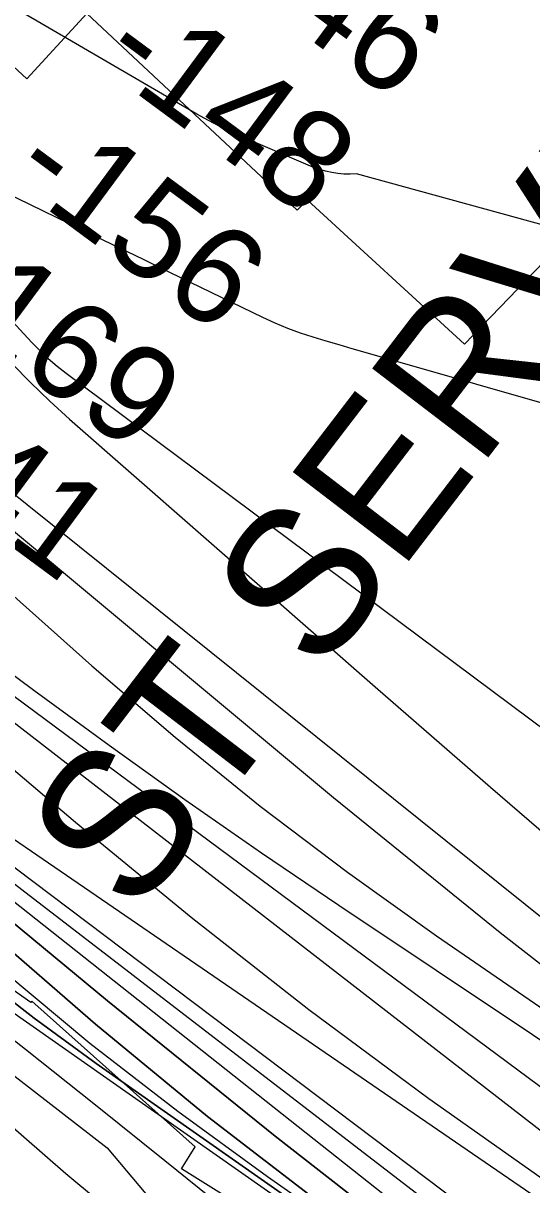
# Model space of a CAD drawing. Extents: x 3651524 to 3689615, y 505651 to 531377.
# Drawn here: x 3659786 to 3660133, y 515628 to 516422 of the extents above; entities that cross this region are included whole.
import ezdxf

# ---------------------------------------------------------------- set-up
doc = ezdxf.new("R2010")
doc.units = 0
for name, color, linetype in [('V-CHAN-NAID', 7, 'Continuous'), ('V-RIVR-RANG', 7, 'Continuous'), ('V-RRAP-FSHR', 7, 'Continuous'), ('V-RRAP-RVMT', 7, 'Continuous'), ('V-TOPO-DPTH', 7, 'Continuous'), ('V-TOPO-MAJR', 7, 'Continuous'), ('V-TOPO-MINR', 7, 'Continuous'), ('V-TOPO-WATR', 7, 'Continuous')]:
    doc.layers.add(name, color=color, linetype=linetype)

msp = doc.modelspace()

# ---------------------------------------------------------------- linework, layer by layer
at = {"layer": 'V-RRAP-FSHR'}
msp.add_lwpolyline([(3659396.851, 515999.135), (3659842.953, 515653.316), (3660038.76, 515420.179), (3660353.083, 515152.532), (3660556.566, 515075.917), (3660792.389, 514981.084), (3661161.297, 514923.914), (3661473.843, 514844.374), (3661744.117, 514711.391), (3661981.087, 514567.222), (3662157.856, 514447.912), (3662424.289, 514303.745)], dxfattribs=at)
at = {"layer": 'V-RRAP-RVMT'}
msp.add_line((3659791.482, 515753.456), (3659790.823, 515752.695), dxfattribs=at)
for points in [[(3659651.793, 516510.376), (3659788.091, 516384.184), (3659829.17, 516428.811), (3659972.803, 516294.337), (3659979.872, 516301.076), (3660087.089, 516202.755), (3660293.017, 516416.547)], [(3659790.823, 515752.695), (3659620.383, 515872.74), (3659609.659, 515863.086), (3659443.462, 515984.102), (3659438.2, 515978.971), (3659260.198, 516110.348), (3659147.603, 516287.133), (3659155.699, 516293.328), (3659039.216, 516470.131)], [(3660212.139, 515294.417), (3660053.726, 515429.09), (3660087.126, 515471.484), (3659930.09, 515612.317), (3659932.054, 515614.896), (3659893.694, 515638.795), (3659903.071, 515653.931), (3659791.482, 515753.456)]]:
    msp.add_lwpolyline(points, dxfattribs=at)
at = {"layer": 'V-TOPO-DPTH'}
for points in [[(3658899.589, 516724.07), (3659568.117, 515898.581), (3659572.31, 515893.572), (3659576.607, 515888.659), (3659581.063, 515883.889), (3659585.624, 515879.213), (3659590.344, 515874.7), (3659595.17, 515870.309), (3659600.157, 515866.1), (3659605.25, 515862.013), (3659691.304, 515795.545), (3659739.384, 515758.163), (3659787.304, 515720.577), (3659834.982, 515682.686), (3659882.5, 515644.592), (3660240.174, 515355.97)], [(3658899.589, 516724.07), (3659568.117, 515898.581), (3659572.31, 515893.572), (3659576.607, 515888.659), (3659581.063, 515883.889), (3659585.624, 515879.213), (3659590.344, 515874.7), (3659595.17, 515870.309), (3659600.157, 515866.1), (3659605.25, 515862.013), (3659691.304, 515795.545), (3659739.384, 515758.163), (3659787.304, 515720.577), (3659834.982, 515682.686), (3659882.5, 515644.592), (3660240.174, 515355.97)], [(3660561.202, 515201.855), (3659835.435, 515710.798), (3659793.122, 515741.866), (3659751.77, 515774.113), (3659711.861, 515808.128), (3659672.914, 515843.323), (3659640.641, 515873.787), (3659618.931, 515894.995), (3659597.723, 515916.676), (3659577.268, 515939.069), (3659557.315, 515961.937), (3659041.277, 516574.153)], [(3660561.202, 515201.855), (3659835.435, 515710.798), (3659793.122, 515741.866), (3659751.77, 515774.113), (3659711.861, 515808.128), (3659672.914, 515843.323), (3659640.641, 515873.787), (3659618.931, 515894.995), (3659597.723, 515916.676), (3659577.268, 515939.069), (3659557.315, 515961.937), (3659041.277, 516574.153)], [(3659203.997, 516455.422), (3659249.099, 516392.961), (3659295.447, 516331.445), (3659342.802, 516270.736), (3659391.669, 516211.237), (3659441.543, 516152.545), (3659606.563, 515963.224), (3659613.614, 515955.573), (3659620.93, 515948.198), (3659628.642, 515941.238), (3659636.618, 515934.556), (3660059.734, 515599.534), (3660149.273, 515529.938)], [(3659203.997, 516455.422), (3659249.099, 516392.961), (3659295.447, 516331.445), (3659342.802, 516270.736), (3659391.669, 516211.237), (3659441.543, 516152.545), (3659606.563, 515963.224), (3659613.614, 515955.573), (3659620.93, 515948.198), (3659628.642, 515941.238), (3659636.618, 515934.556), (3660059.734, 515599.534), (3660149.273, 515529.938)], [(3659193.993, 516433.801), (3659232.704, 516384.43), (3659272.616, 516336.025), (3659313.331, 516288.265), (3659597.717, 515962.858), (3659607.129, 515952.6), (3659616.854, 515942.662), (3659627.047, 515933.206), (3659637.553, 515924.071), (3659843.231, 515753.783), (3659957.9, 515661.174), (3660074.019, 515570.468), (3660192.31, 515482.615)], [(3660192.31, 515482.615), (3660074.019, 515570.468), (3659957.9, 515661.174), (3659843.231, 515753.783), (3659637.553, 515924.071), (3659627.047, 515933.206), (3659616.854, 515942.662), (3659607.129, 515952.6), (3659597.717, 515962.858), (3659313.331, 516288.265), (3659272.616, 516336.025), (3659232.704, 516384.43), (3659193.993, 516433.801)], [(3659180.088, 516429.198), (3659588.863, 515962.484), (3659600.589, 515949.567), (3659612.61, 515936.939), (3659625.072, 515924.746), (3659637.827, 515912.843), (3659759.825, 515802.994), (3659834.938, 515737.814), (3659911.561, 515674.532), (3659990.449, 515614.098), (3660070.848, 515555.562), (3660572.282, 515204.361)], [(3660572.282, 515204.361), (3660070.848, 515555.562), (3659990.449, 515614.098), (3659911.561, 515674.532), (3659834.938, 515737.814), (3659759.825, 515802.994), (3659637.827, 515912.843), (3659625.072, 515924.746), (3659612.61, 515936.939), (3659600.589, 515949.567), (3659588.863, 515962.484), (3659180.088, 516429.198)]]:
    msp.add_lwpolyline(points, dxfattribs=at)
at = {"layer": 'V-TOPO-MAJR'}
for points in [[(3660956.257, 516059.962), (3660013.267, 516319.219), (3660009.034, 516318.975), (3660004.814, 516318.99), (3660000.613, 516319.392), (3659996.425, 516320.053), (3659992.285, 516321.035), (3659988.196, 516322.18), (3659984.185, 516323.57), (3659980.224, 516325.123), (3659936.905, 516343.645), (3659928.575, 516347.392), (3659920.346, 516351.34), (3659912.27, 516355.592), (3659904.295, 516360.045), (3659720.25, 516467.359)], [(3659368.191, 516459.155), (3659420.277, 516387.593), (3659471.403, 516315.318), (3659556.923, 516191.782), (3659564.525, 516180.71), (3659572.069, 516169.598), (3659579.527, 516158.429), (3659586.927, 516147.22), (3659594.524, 516136.166), (3659602.436, 516125.354), (3659610.825, 516114.908), (3659619.53, 516104.704), (3659673.997, 516043.678), (3659678.993, 516038.414), (3659684.188, 516033.368), (3659689.682, 516028.648), (3659695.375, 516024.147), (3660621.19, 515337.071)], [(3659546.094, 516453.45), (3659571.779, 516419.553), (3659598.852, 516386.755), (3659626.851, 516354.689), (3659765.241, 516202.7), (3659777.769, 516189.395), (3659790.583, 516176.381), (3659803.824, 516163.802), (3659817.35, 516151.514), (3659947.204, 516037.454), (3660026.008, 515968.511), (3660104.993, 515899.777), (3660184.25, 515831.357)], [(3659235.003, 516451.101), (3659274.641, 516394.713), (3659314.807, 516338.69), (3659364.764, 516270.025), (3659405.663, 516215.315), (3659447.485, 516161.339), (3659490.691, 516108.465), (3659534.82, 516056.324), (3659615.398, 515963.581), (3659620.073, 515958.515), (3659624.936, 515953.649), (3659630.082, 515949.082), (3659635.416, 515944.715), (3660311.335, 515424.312)]]:
    msp.add_lwpolyline(points, dxfattribs=at)
at = {"layer": 'V-TOPO-MINR'}
for points in [[(3658970.75, 516648.522), (3659549.511, 515948.184), (3659568.629, 515925.82), (3659588.227, 515903.9), (3659608.546, 515882.646), (3659629.344, 515861.835), (3659650.947, 515841.895), (3659673.137, 515822.666), (3659696.21, 515804.505), (3659719.87, 515787.056), (3660555.664, 515200.604)], [(3659041.277, 516574.153), (3659557.315, 515961.937), (3659577.268, 515939.069), (3659597.723, 515916.676), (3659618.931, 515894.995), (3659640.641, 515873.787), (3659672.914, 515843.323), (3659711.861, 515808.128), (3659751.77, 515774.113), (3659793.122, 515741.866), (3659835.435, 515710.798), (3660561.202, 515201.855)], [(3659111.116, 516500.99), (3659574.163, 515962.172), (3659589.741, 515944.672), (3659605.711, 515927.551), (3659622.268, 515910.997), (3659639.217, 515894.822), (3659716.406, 515823.691), (3659773.198, 515773.419), (3659831.257, 515724.722), (3659891.218, 515678.385), (3659952.445, 515633.622), (3660566.742, 515203.107)], [(3659338.624, 516463.63), (3659384.563, 516399.642), (3659447.143, 516310.674), (3659461.087, 516290.646), (3659474.903, 516270.531), (3659488.527, 516250.286), (3659502.022, 516229.952), (3659515.849, 516209.883), (3659530.247, 516190.252), (3659545.499, 516171.277), (3659561.321, 516152.739), (3659659.251, 516043.018), (3659668.232, 516033.496), (3659677.539, 516024.324), (3659687.334, 516015.676), (3659697.456, 516007.377), (3660161.927, 515647.448)], [(3659101.398, 516453.858), (3659543.399, 515883.69), (3659551.15, 515874.223), (3659559.217, 515865.049), (3659567.761, 515856.316), (3659576.621, 515847.878), (3659728.439, 515710.79), (3659814.714, 515635.609), (3659902.672, 515562.53), (3659993.157, 515492.603), (3660085.326, 515424.778), (3660520.018, 515116.583)], [(3659203.997, 516455.422), (3659249.099, 516392.961), (3659295.447, 516331.445), (3659342.802, 516270.736), (3659391.669, 516211.237), (3659441.543, 516152.545), (3659606.563, 515963.224), (3659613.614, 515955.573), (3659620.93, 515948.198), (3659628.642, 515941.238), (3659636.618, 515934.556), (3660059.734, 515599.534), (3660149.273, 515529.938)], [(3659432.2, 516457.485), (3659461.448, 516419.304), (3659490.529, 516380.996), (3659519.568, 516342.654), (3659548.715, 516304.395), (3659578.025, 516266.261), (3659607.444, 516228.21), (3659688.305, 516124.081), (3659704.987, 516103.778), (3659722.371, 516084.132), (3659740.809, 516065.472), (3659759.949, 516047.468), (3659832.582, 515982.82), (3659889.436, 515934.095), (3659947.444, 515886.842), (3660007.183, 515841.796), (3660068.074, 515798.221), (3660676.381, 515379.934)], [(3659460.762, 516460.262), (3659560.278, 516331.812), (3659574.569, 516313.235), (3659588.775, 516294.593), (3659602.852, 516275.855), (3659616.844, 516257.052), (3659630.96, 516238.35), (3659645.328, 516219.847), (3659660.074, 516201.644), (3659675.07, 516183.64), (3659725.886, 516123.893), (3659732.882, 516116.085), (3659740.13, 516108.531), (3659747.757, 516101.36), (3659755.636, 516094.444), (3659997.641, 515892.815), (3660111.624, 515800.418), (3660227.199, 515710.116)], [(3659406.263, 516448.201), (3659452.45, 516385.522), (3659497.413, 516321.96), (3659541.56, 516257.808), (3659665.778, 516073.504), (3659667.241, 516071.323), (3659668.697, 516069.137), (3659670.144, 516066.944), (3659671.583, 516064.748), (3659673.065, 516062.584), (3659674.61, 516060.468), (3659676.249, 516058.424), (3659677.951, 516056.428), (3659688.743, 516044.338), (3659689.729, 516043.298), (3659692.961, 516040.479), (3659792.957, 515966.115), (3659844.386, 515928.469), (3659896.184, 515891.347), (3659948.536, 515855.012), (3660001.259, 515819.201), (3660663.59, 515376.593)], [(3659506.762, 516443.419), (3659572.64, 516356.954), (3659732.98, 516145.365), (3659734.331, 516143.57), (3659737.004, 516139.96), (3659739.668, 516136.344), (3659742.458, 516132.829), (3659743.908, 516131.114), (3659749.52, 516124.655), (3659752.397, 516121.887), (3660343.163, 515647.46)], [(3659193.993, 516433.801), (3659232.704, 516384.43), (3659272.616, 516336.025), (3659313.331, 516288.265), (3659597.717, 515962.858), (3659607.129, 515952.6), (3659616.854, 515942.662), (3659627.047, 515933.206), (3659637.553, 515924.071), (3659843.231, 515753.783), (3659957.9, 515661.174), (3660074.019, 515570.468), (3660192.31, 515482.615)], [(3659277.146, 516432.327), (3659309.733, 516384.43), (3659342.893, 516336.928), (3659376.435, 516289.689), (3659506.522, 516108.792), (3659525.703, 516082.864), (3659545.339, 516057.295), (3659565.657, 516032.265), (3659586.43, 516007.594), (3659624.219, 515963.925), (3659626.513, 515961.438), (3659628.905, 515959.054), (3659631.442, 515956.826), (3659634.077, 515954.702), (3660572.832, 515245.86)], [(3659305.376, 516435.237), (3659331.43, 516396.23), (3659357.519, 516357.246), (3659383.893, 516318.46), (3659410.696, 516279.969), (3659437.785, 516241.674), (3659630.56, 515972.34), (3659632.625, 515969.591), (3659634.77, 515966.909), (3659637.036, 515964.328), (3659639.382, 515961.815), (3659641.854, 515959.431), (3659644.413, 515957.148), (3659647.101, 515955.02), (3659649.875, 515952.995), (3660616.218, 515290.126)], [(3659336.726, 516430.478), (3659357.082, 516401.318), (3659377.253, 516372.032), (3659397.147, 516342.557), (3659416.855, 516312.956), (3659436.952, 516283.657), (3659457.751, 516254.884), (3659479.601, 516226.902), (3659502.152, 516199.447), (3659635.918, 516042.609), (3659651.014, 516025.757), (3659666.625, 516009.423), (3659683.01, 515993.865), (3659699.911, 515978.824), (3659821.429, 515875.863), (3659900.431, 515810.981), (3659980.702, 515747.761), (3660062.874, 515687.034), (3660146.315, 515627.969)], [(3659180.088, 516429.198), (3659588.863, 515962.484), (3659600.589, 515949.567), (3659612.61, 515936.939), (3659625.072, 515924.746), (3659637.827, 515912.843), (3659759.825, 515802.994), (3659834.938, 515737.814), (3659911.561, 515674.532), (3659990.449, 515614.098), (3660070.848, 515555.562), (3660572.282, 515204.361)], [(3660170.586, 516153.626), (3660019.207, 516196.979), (3660010.331, 516199.543), (3660001.463, 516202.134), (3659992.607, 516204.766), (3659983.759, 516207.424), (3659974.997, 516210.307), (3659966.34, 516213.46), (3659957.842, 516217.018), (3659949.45, 516220.846), (3659878.715, 516255.156), (3659867.785, 516260.46), (3659856.856, 516265.766), (3659845.929, 516271.075), (3659835.002, 516276.386), (3659693.125, 516345.372)], [(3659721.268, 516279.865), (3659791.516, 516203.927), (3659797.031, 516198.284), (3659802.74, 516192.857), (3659808.739, 516187.751), (3659814.931, 516182.86), (3660726.792, 515502.539)]]:
    msp.add_lwpolyline(points, dxfattribs=at)
at = {"layer": 'V-TOPO-WATR'}
msp.add_lwpolyline([(3658899.589, 516724.07), (3659568.117, 515898.581), (3659572.31, 515893.572), (3659576.607, 515888.659), (3659581.063, 515883.889), (3659585.624, 515879.213), (3659590.344, 515874.7), (3659595.17, 515870.309), (3659600.157, 515866.1), (3659605.25, 515862.013), (3659691.304, 515795.545), (3659739.384, 515758.163), (3659787.304, 515720.577), (3659834.982, 515682.686), (3659882.5, 515644.592), (3660240.174, 515355.97)], dxfattribs=at)

# ---------------------------------------------------------------- texts
at = {"layer": 'V-CHAN-NAID'}
msp.add_text('ST SERVICES (101.4) (2)', height=100, rotation=52.555239, dxfattribs=at).set_placement((3659861.831, 515809.781))
at = {"layer": 'V-RIVR-RANG'}
for s, p in [('-146', (3659895.454, 516474.513)), ('-148', (3659835.371, 516394.573)), ('-156', (3659774.439, 516315.259)), ('-169', (3659716.688, 516233.593)), ('-141', (3659668.058, 516145.183))]:
    msp.add_text(s, height=67, rotation=323.515472, dxfattribs=at).set_placement(p)

doc.saveas('drawing.dxf')
